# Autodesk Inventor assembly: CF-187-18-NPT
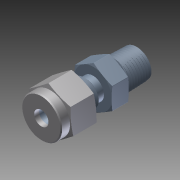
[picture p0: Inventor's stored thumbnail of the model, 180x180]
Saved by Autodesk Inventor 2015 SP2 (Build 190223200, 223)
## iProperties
Created: 2017-10
Part Number: CF-187-18-NPT
Document SubType Name: Assembly
Designer: JN
Author: JN
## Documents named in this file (5)
- C:\Users\JN\Documents\CAD Drawings\The Sensor Connection\3D\CF\CF-0250-18-NPT\3D\CF-187-18-NPT.iam
- C:\Users\JN\Documents\CAD Drawings\The Sensor Connection\3D\CF\CF-0250-18-NPT\3D\Imported Components\CF-0187-NPT Bottom Ferrule\CF-0187-NPT Bottom Ferrule.ipt
- C:\Users\JN\Documents\CAD Drawings\The Sensor Connection\3D\CF\CF-0250-18-NPT\3D\Imported Components\CF-0187-NPT Cap\CF-0187-NPT Cap.ipt
- C:\Users\JN\Documents\CAD Drawings\The Sensor Connection\3D\CF\CF-0250-18-NPT\3D\Imported Components\CF-0187-NPT Top Ferrule\CF-0187-NPT Top Ferrule.ipt
- C:\Users\JN\Documents\CAD Drawings\The Sensor Connection\3D\CF\CF-0250-18-NPT\3D\Imported Components\CF-0187-18-NPT Threaded Body\CF-0187-18-NPT Threaded Body.ipt
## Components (4 placed, 4 different names)
1. CF-0187-NPT Bottom Ferrule:1 — Mate:3, Mate:4, Mate:7, Mate:8
2. CF-0187-NPT Cap:1 — Mate:5, Mate:6, Rotation:1
3. CF-0187-NPT Top Ferrule:1 — Mate:3, Mate:4, Mate:5, Mate:6
4. CF-0187-18-NPT Threaded Body:1 — Mate:7, Mate:8, Rotation:1
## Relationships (7: Mate 6, RelateRotation 1)
- Mate:3: CF-0187-NPT Bottom Ferrule:1 ↔ CF-0187-NPT Top Ferrule:1
- Mate:4: CF-0187-NPT Bottom Ferrule:1 ↔ CF-0187-NPT Top Ferrule:1
- Mate:5: CF-0187-NPT Cap:1 ↔ CF-0187-NPT Top Ferrule:1
- Mate:6: CF-0187-NPT Cap:1 ↔ CF-0187-NPT Top Ferrule:1
- Mate:7: CF-0187-NPT Bottom Ferrule:1 ↔ CF-0187-18-NPT Threaded Body:1
- Mate:8: CF-0187-NPT Bottom Ferrule:1 ↔ CF-0187-18-NPT Threaded Body:1
- Rotation:1 [RelateRotation]: CF-0187-NPT Cap:1 ↔ CF-0187-18-NPT Threaded Body:1
